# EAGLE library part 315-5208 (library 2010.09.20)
Sega 315-5208 Paging Chip The 315-5208 paging chip can handle up to 8 &times; 16KByte memory pages, making it suitable for use with 1 Megabit games. The commercial SMS cartridges that use the 315-5208 for paging use a ROM chip with model number 831000. The 831000 is a 28-pin 256K&times; 8 ROM chip. Replacing a #831000 ROM with an #27010 EPROM A 28-pin #831000 ROM can be replaced with a #27010 32-pin 1 Megabit EPROM. The followingtable indicates the correct pin mapping. 831000 ROM Pin27010 EPROM Pin 1-143-16 15-2117-23 23-2825-30 222 Connect pins 1, 31, and 32 of the 27010 EPROM to +5v, and pin 24 to GROUND. Information in this document is compiled from postings by Mike G. and Charles Mac Donald on the S8-Dev Forum, and from personal investigations by Zoop and Eric Quinn. Drawn in Eagle by Darren Lue Choy 2010.09.20
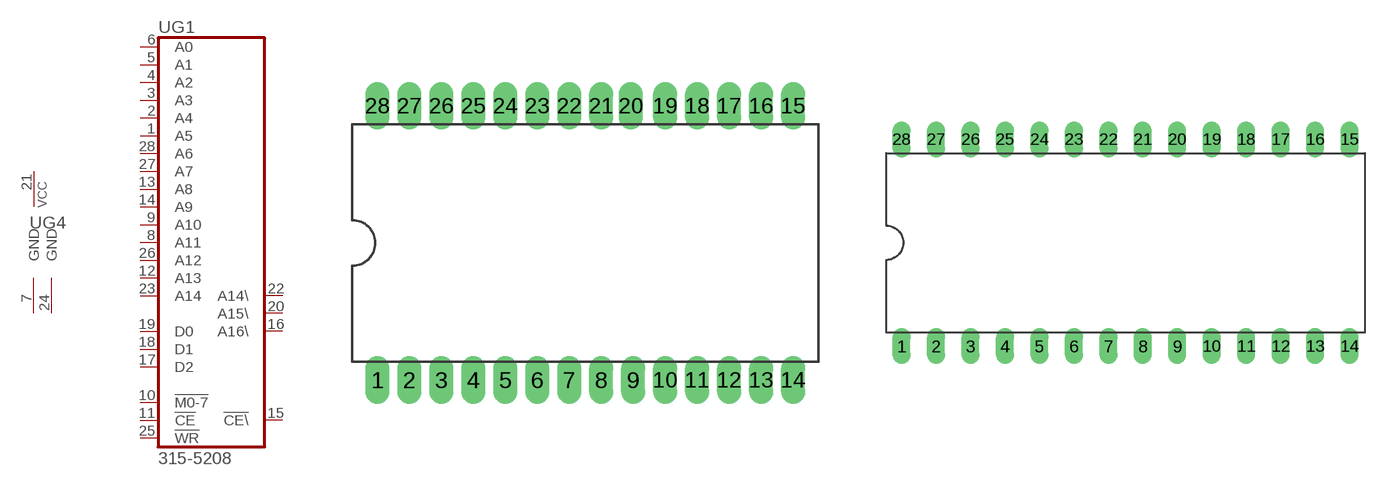
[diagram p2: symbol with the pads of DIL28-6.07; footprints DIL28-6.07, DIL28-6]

Designator prefix -; gates G1=315-5208 G2=PWRGND G3=PWRGND G4=PWRVCC

## 315-5208-6.07  [DIL28-6.07]
1  G1:A5  in
2  G1:A4  in
3  G1:A3  in
4  G1:A2  in
5  G1:A1  in
6  G1:A0  in
7  G2:GND  pwr
8  G1:A11  in
9  G1:A10  in
10  G1:!M0-7  in
11  G1:!CE  in
12  G1:A13  in
13  G1:A8  in
14  G1:A9  in
15  G1:!CE\  out
16  G1:A16\  out
17  G1:D2  in
18  G1:D1  in
19  G1:D0  in
20  G1:A15\  out
21  G4:VCC  pwr
22  G1:A14\  out
23  G1:A14  in
24  G3:GND  pwr
25  G1:!WR  in
26  G1:A12  in
27  G1:A7  in
28  G1:A6  in

## 315-5208  [DIL28-6]
Pads as for DIL28-6.07

## Footprint DIL28-6.07 (pad centres in mm)
Dual In Line Package 0.6 inch 0.07 pitch Drawn by D Lue Choy &micro; 2010.09.20
drill 0.813 long: 1 -11.557,-7.62; 2 -9.779,-7.62; 3 -8.001,-7.62; 4 -6.223,-7.62; 5 -4.445,-7.62; 6 -2.667,-7.62; 7 -0.889,-7.62; 8 0.889,-7.62; 9 2.667,-7.62; 10 4.445,-7.62; 11 6.223,-7.62; 12 8.001,-7.62; 13 9.779,-7.62; 14 11.557,-7.62; 15 11.557,7.62; 16 9.779,7.62; 17 8.001,7.62; 18 6.223,7.62; 19 4.445,7.62; 20 2.54,7.62; 21 0.889,7.62; 22 -0.889,7.62; 23 -2.667,7.62; 24 -4.445,7.62; 25 -6.223,7.62; 26 -8.001,7.62; 27 -9.779,7.62; 28 -11.557,7.62

## Footprint DIL28-6 (pad centres in mm)
Dual In Line Package 0.6 inch
drill 0.813 long: 1 -16.51,-7.62; 2 -13.97,-7.62; 3 -11.43,-7.62; 4 -8.89,-7.62; 5 -6.35,-7.62; 6 -3.81,-7.62; 7 -1.27,-7.62; 8 1.27,-7.62; 9 3.81,-7.62; 10 6.35,-7.62; 11 8.89,-7.62; 12 11.43,-7.62; 13 13.97,-7.62; 14 16.51,-7.62; 15 16.51,7.62; 16 13.97,7.62; 17 11.43,7.62; 18 8.89,7.62; 19 6.35,7.62; 20 3.81,7.62; 21 1.27,7.62; 22 -1.27,7.62; 23 -3.81,7.62; 24 -6.35,7.62; 25 -8.89,7.62; 26 -11.43,7.62; 27 -13.97,7.62; 28 -16.51,7.62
